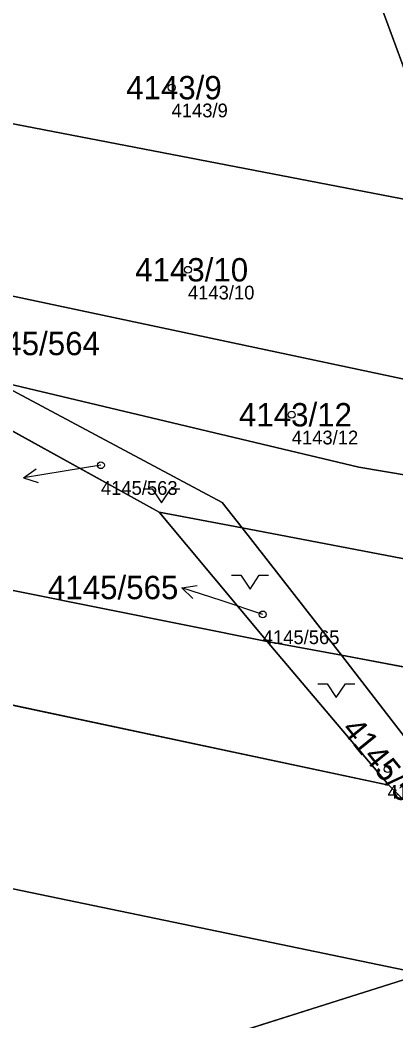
# Model space of a CAD drawing. Extents: x -739214 to -733252, y -1147612 to -1142842.
# Drawn here: x -735990.2 to -735962.8, y -1146702.1 to -1146629.3 of the extents above; entities that cross this region are included whole.
import ezdxf

# ---------------------------------------------------------------- set-up
doc = ezdxf.new("R2010")
doc.units = 0
for name, color, linetype in [('Definiční body', 7, 'Continuous'), ('Hranice parcel', 7, 'Continuous'), ('Parcelní čísla', 7, 'Continuous'), ('Polygon parcely', 7, 'Continuous'), ('Pop  PČ popisy', 7, 'Continuous'), ('Značky kultur', 7, 'Continuous')]:
    doc.layers.add(name, color=color, linetype=linetype)

msp = doc.modelspace()

# ---------------------------------------------------------------- linework, layer by layer
at = {"layer": 'Definiční body'}
for centre in [(-735979.15, -1146634.25), (-735977.96, -1146647.49), (-735970.41, -1146658.03), (-735984.29, -1146661.7), (-735972.52, -1146672.55), (-735963.44, -1146683.79)]:
    msp.add_circle(centre, 0.25, dxfattribs=at)
at = {"layer": 'Hranice parcel'}
for p, q in [((-735963.77, -1146628.74), (-735958.48, -1146643.08)), ((-735998.5, -1146635.37), (-735958.48, -1146643.08)), ((-736000.07, -1146647.41), (-735946.13, -1146658.87)), ((-735980.05, -1146665.11), (-736001.45, -1146653.31)), ((-735963.34, -1146684.95), (-736099.42, -1146656.08)), ((-735972.21, -1146674.51), (-735980.05, -1146665.11)), ((-735980.05, -1146665.11), (-735974.01, -1146666.26)), ((-735960.89, -1146698.69), (-736116.2, -1146666.46)), ((-735974.01, -1146666.26), (-735938.77, -1146672.98)), ((-735974.01, -1146666.26), (-735966.8, -1146675.52)), ((-735972.21, -1146674.51), (-735966.8, -1146675.52)), ((-735972.21, -1146674.51), (-735963.34, -1146684.95)), ((-735966.8, -1146675.52), (-735937.31, -1146681.05)), ((-735966.8, -1146675.52), (-735962.03, -1146681.66)), ((-735963.34, -1146684.95), (-735954.46, -1146693.89)), ((-735960.89, -1146698.69), (-735993.5, -1146708.99))]:
    msp.add_line(p, q, dxfattribs=at)
for points in [[(-736089.74, -1146650.09), (-736037.76, -1146661.36), (-735972.21, -1146674.51)], [(-735941.26, -1146665.94), (-735965.52, -1146661.84), (-735992.16, -1146655.51)], [(-735992.16, -1146655.51), (-735975.46, -1146664.4), (-735974.01, -1146666.26)]]:
    msp.add_lwpolyline(points, dxfattribs=at)
at = {"layer": 'Polygon parcely'}
for points in [[(-735970.08, -1146615.6), (-735965.79, -1146622.93), (-735963.77, -1146628.74), (-735958.48, -1146643.08), (-735946.13, -1146658.87), (-735941.26, -1146665.94), (-735944.02, -1146658.17), (-735953.45, -1146642.76), (-735969.56, -1146611.93), (-735984.67, -1146586.96), (-735989.62, -1146578.34), (-735979.56, -1146600.82)], [(-735998.5, -1146635.37), (-735958.48, -1146643.08), (-735963.77, -1146628.74), (-735996.43, -1146622.27)], [(-736000.07, -1146647.41), (-735946.13, -1146658.87), (-735958.48, -1146643.08), (-735998.5, -1146635.37), (-735998.83, -1146637.45)], [(-735980.05, -1146665.11), (-736001.45, -1146653.31), (-736076.17, -1146637.88), (-736077.42, -1146642.47), (-736089.74, -1146650.09), (-736037.76, -1146661.36), (-735972.21, -1146674.51)], [(-735992.16, -1146655.51), (-735965.52, -1146661.84), (-735941.26, -1146665.94), (-735946.13, -1146658.87), (-736000.07, -1146647.41), (-736000.52, -1146651.07)], [(-736089.74, -1146650.09), (-736099.42, -1146656.08), (-735963.34, -1146684.95), (-735972.21, -1146674.51), (-736037.76, -1146661.36)], [(-735974.01, -1146666.26), (-735975.46, -1146664.4), (-735992.16, -1146655.51), (-736001.45, -1146653.31), (-735980.05, -1146665.11)], [(-735974.01, -1146666.26), (-735938.77, -1146672.98), (-735941.26, -1146665.94), (-735965.52, -1146661.84), (-735992.16, -1146655.51), (-735975.46, -1146664.4)], [(-736099.42, -1146656.08), (-736116.2, -1146666.46), (-735960.89, -1146698.69), (-735954.46, -1146693.89), (-735963.34, -1146684.95)], [(-735972.21, -1146674.51), (-735966.8, -1146675.52), (-735974.01, -1146666.26), (-735980.05, -1146665.11)], [(-736116.2, -1146666.46), (-736124.81, -1146671.78), (-736132.77, -1146682.87), (-735993.5, -1146708.99), (-735960.89, -1146698.69)], [(-735966.8, -1146675.52), (-735937.31, -1146681.05), (-735938.09, -1146674.9), (-735938.77, -1146672.98), (-735974.01, -1146666.26)], [(-735954.46, -1146693.89), (-735953.23, -1146692.97), (-735962.03, -1146681.66), (-735966.8, -1146675.52), (-735972.21, -1146674.51), (-735963.34, -1146684.95)], [(-735962.03, -1146681.66), (-735953.23, -1146692.97), (-735937.31, -1146681.05), (-735966.8, -1146675.52)], [(-735947.49, -1146700.89), (-735960.89, -1146698.69), (-735993.5, -1146708.99), (-735949.02, -1146717.49), (-735941.86, -1146713.69)]]:
    msp.add_lwpolyline(points, close=True, dxfattribs=at)
at = {"layer": 'Pop  PČ popisy'}
for p, q in [((-735989.914, -1146662.609), (-735989.003, -1146661.958)), ((-735986.95, -1146662.14), (-735989.914, -1146662.609)), ((-735984.29, -1146661.7), (-735986.95, -1146662.14)), ((-735989.914, -1146662.609), (-735988.847, -1146662.947)), ((-735978.404, -1146670.613), (-735977.297, -1146670.446)), ((-735975.55, -1146671.54), (-735978.404, -1146670.613)), ((-735978.404, -1146670.613), (-735977.606, -1146671.398)), ((-735972.52, -1146672.55), (-735975.55, -1146671.54))]:
    msp.add_line(p, q, dxfattribs=at)
at = {"layer": 'Značky kultur'}
for p, q in [((-735981.22, -1146663.425), (-735980.55, -1146663.425)), ((-735980.55, -1146663.425), (-735979.88, -1146664.43)), ((-735979.88, -1146664.43), (-735979.21, -1146663.425)), ((-735979.21, -1146663.425), (-735978.54, -1146663.425)), ((-735974.78, -1146669.695), (-735974.11, -1146669.695)), ((-735974.11, -1146669.695), (-735973.44, -1146670.7)), ((-735973.44, -1146670.7), (-735972.77, -1146669.695)), ((-735972.77, -1146669.695), (-735972.1, -1146669.695)), ((-735968.51, -1146677.585), (-735967.84, -1146677.585)), ((-735967.84, -1146677.585), (-735967.17, -1146678.59)), ((-735967.17, -1146678.59), (-735966.5, -1146677.585)), ((-735966.5, -1146677.585), (-735965.83, -1146677.585))]:
    msp.add_line(p, q, dxfattribs=at)

# ---------------------------------------------------------------- texts
at = {"layer": 'Definiční body'}
for s, p in [('4143/9', (-735979.15, -1146636.406)), ('4143/10', (-735977.96, -1146649.646)), ('4143/12', (-735970.41, -1146660.186)), ('4145/563', (-735984.29, -1146663.856)), ('4145/565', (-735972.52, -1146674.706)), ('4145/566', (-735963.44, -1146685.946))]:
    msp.add_text(s, height=1, dxfattribs=at).set_placement(p)
at = {"layer": 'Parcelní čísla'}
for s, p in [('4143/9', (-735982.455, -1146635.1)), ('4143/10', (-735981.798, -1146648.34)), ('4145/564', (-735993.84, -1146653.7)), ('4143/12', (-735974.248, -1146658.88)), ('4145/565', (-735988.14, -1146671.44))]:
    msp.add_text(s, height=1.7, dxfattribs=at).set_placement(p)
msp.add_text('4145/566', height=1.7, rotation=309, dxfattribs=at).set_placement((-735966.85, -1146680.928))

doc.saveas('drawing.dxf')
